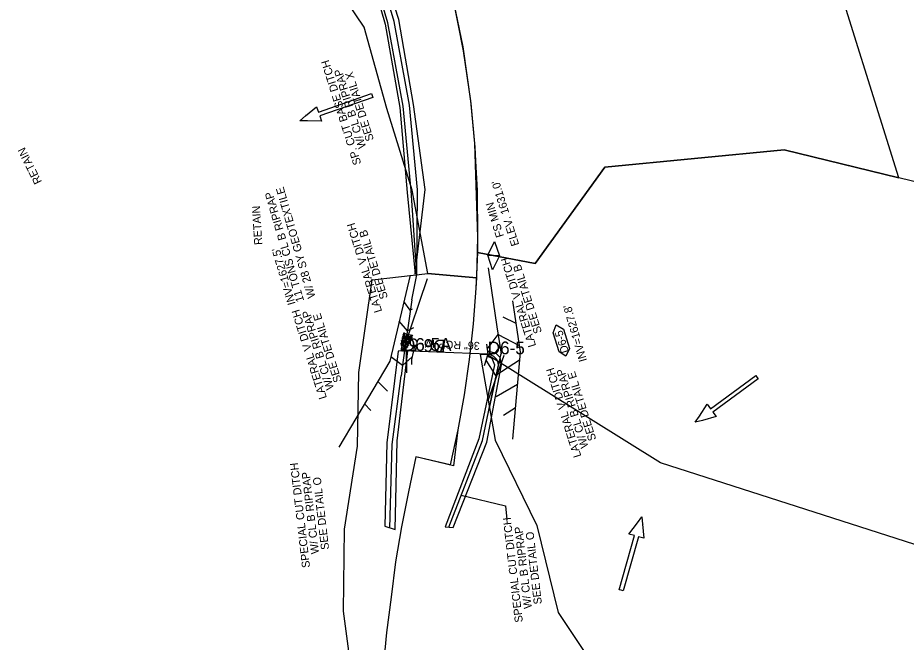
# Model space of a CAD drawing. Extents: x 465700 to 483515, y 488970 to 507540.
# Drawn here: x 474377 to 474932, y 504423 to 504814 of the extents above; entities that cross this region are included whole.
import ezdxf

# ---------------------------------------------------------------- set-up
doc = ezdxf.new("R2010")
doc.units = 0
for name, color, linetype in [('Default', 7, 'Continuous'), ('Exist Plan Preparation Drainage Flow Arrows', 7, 'Continuous'), ('Exist Plan Preparation Watershed Blue', 7, 'Continuous'), ('Prop Drainage Structure Box Number Symbol CELL', 7, 'Continuous'), ('Prop Drainage Structure Pipe Collar Label', 7, 'Continuous'), ('Prop Drainage Structure Pipe RCP 36in Class IV', 7, 'Continuous'), ('Prop Drainage Structure Pipe RCP 36in Class IV Label', 7, 'Continuous'), ('Prop Drainage Structure Pipe Stub Out CELL', 7, 'Continuous'), ('Prop Drainage Structure Tops and Inverts LABEL', 7, 'Continuous'), ('Prop Earthen Structure Ditch Flow Line', 7, 'Continuous'), ('Prop Earthen Structure False Sump CELL', 7, 'Continuous'), ('Prop Earthen Structure False Sump Label', 7, 'Continuous'), ('Prop Earthen Structure Head Ditch', 7, 'Continuous'), ('Prop Erosion Embankment Toe Protection Label', 7, 'Continuous'), ('Prop Erosion Rip Rap Class B', 7, 'Continuous'), ('Prop Erosion Rip Rap Pad at Outlet CELL', 7, 'Continuous'), ('Prop Erosion Rip Rap Pad at Outlet Label', 7, 'Continuous'), ('Scratch_Level_4', 7, 'Continuous'), ('Scratch_Level_8', 7, 'Continuous')]:
    doc.layers.add(name, color=color, linetype=linetype)

# ---------------------------------------------------------------- blocks, each defined once
blk = doc.blocks.new('Existing ground flow arrow')
at = {"layer": 'Default'}
blk.add_line((2.5, -4.33), (2.5, -4.33), dxfattribs=at)
blk.add_lwpolyline([(-1.29, -47.2), (-1.28, -12.53), (-4.77, -12.53), (-1.65, -4.33), (0, 0), (1.65, -4.33), (4.78, -12.53), (1.28, -12.52), (1.29, -47.19), (0, -47.2)], close=True, dxfattribs=at)

msp = doc.modelspace()

# ---------------------------------------------------------------- linework, layer by layer
at = {"layer": 'Exist Plan Preparation Watershed Blue'}
for points in [[(474648.84, 504827.06), (474655.42, 504793.19), (474660.02, 504761.97), (474662.56, 504735.22), (474664.49, 504676.57), (474664.34, 504667.15), (474700.48, 504660.25), (474743.93, 504720.52), (474855.94, 504731.27), (474927.77, 504713.75), (474882, 504859.82)], [(475570.4, 504291.05), (475350.2, 504505.26), (475188.14, 504513.08), (475042.86, 504685.67), (474855.94, 504731.27), (474743.93, 504720.52), (474700.48, 504660.25), (474664.34, 504667.15), (474663.39, 504644.79), (474661.7, 504622.49), (474659.24, 504600.25), (474656.04, 504578.11), (474652.08, 504556.09), (474649.34, 504533.77), (474625.96, 504539.2), (474621.18, 504517.45), (474616.94, 504495.59), (474613.24, 504473.63), (474610.4, 504451.46), (474607.44, 504429.48), (474605.35, 504407.31)]]:
    msp.add_lwpolyline(points, dxfattribs=at)
at = {"layer": 'Prop Drainage Structure Box Number Symbol CELL'}
msp.add_lwpolyline([(474715.42, 504604.91), (474711.65, 504616.94), (474713.51, 504621.82), (474718.1, 504619.12), (474721.87, 504607.09), (474719.65, 504602.21), (474715.42, 504604.91)], dxfattribs=at)
at = {"layer": 'Prop Drainage Structure Pipe RCP 36in Class IV'}
msp.add_line((474670.78, 504603.4), (474617.78, 504605.54), dxfattribs=at)
at = {"layer": 'Prop Drainage Structure Pipe Stub Out CELL'}
msp.add_line((474670.78, 504603.4), (474670.78, 504603.4), dxfattribs=at)
msp.add_line((474670.78, 504603.4), (474670.78, 504603.4), dxfattribs=at)
msp.add_lwpolyline([(474670.77, 504603.4), (474670.79, 504603.42), (474670.8, 504603.4), (474670.78, 504603.39), (474670.77, 504603.4)], dxfattribs=at)
at = {"layer": 'Prop Earthen Structure Ditch Flow Line'}
for p, q in [((474626.39, 504653.19), (474626.84, 504706.28)), ((474671.03, 504657.44), (474676.54, 504620.59))]:
    msp.add_line(p, q, dxfattribs=at)
for points in [[(474622.86, 504705.91), (474617.92, 504758.57), (474608.42, 504810.58), (474593.3, 504861.45), (474572.32, 504910.74)], [(474626.84, 504706.28), (474621.89, 504759.11), (474612.32, 504811.51), (474597.07, 504862.8), (474576, 504912.31)], [(474623.27, 504637.38), (474626.39, 504653.19), (474622.86, 504705.91)], [(474609.67, 504494.69), (474611.07, 504546.92), (474616.75, 504589.94)], [(474646.4, 504495.4), (474667.45, 504549.43), (474674.28, 504581.38)]]:
    msp.add_lwpolyline(points, dxfattribs=at)
at = {"layer": 'Prop Earthen Structure False Sump CELL'}
msp.add_lwpolyline([(474673.71, 504656.14), (474670.78, 504665.4), (474675.04, 504674.02), (474678.14, 504664.92), (474670.78, 504665.4), (474678.14, 504664.92), (474673.71, 504656.14)], dxfattribs=at)
at = {"layer": 'Prop Earthen Structure Head Ditch'}
for p, q in [((474632.84, 504650.7), (474617.77, 504605.54)), ((474632.84, 504650.7), (474617.77, 504605.54)), ((474623.27, 504637.38), (474618.04, 504599.72)), ((474619.8, 504605.47), (474620.11, 504591.74)), ((474671, 504574.44), (474680.98, 504602.77)), ((474618.04, 504599.72), (474616.75, 504589.94))]:
    msp.add_line(p, q, dxfattribs=at)
for points in [[(474622.22, 504652.8), (474609.63, 504599.13), (474577.65, 504545.43)], [(474623.66, 504631.7), (474622.38, 504630.94), (474618.39, 504636.48)], [(474686.32, 504636.79), (474691.15, 504604.83), (474686.28, 504550.27)], [(474680.25, 504626.78), (474688.42, 504622.94)], [(474624.47, 504619.93), (474620.59, 504618.08), (474615.51, 504624.18)], [(474676.54, 504620.59), (474678.29, 504608.9)], [(474676.54, 504620.59), (474679.09, 504603.53)], [(474670.48, 504606.6), (474677.3, 504615.83), (474690.53, 504608.97)], [(474625.19, 504609.42), (474623.13, 504600.14), (474623.06, 504597.12)], [(474670, 504609.75), (474670.9, 504603.41), (474668.55, 504596.22)], [(474671.8, 504569.8), (474679.11, 504603.98)], [(474623.49, 504601.77), (474617.51, 504596.41), (474610.28, 504601.9)], [(474690.69, 504599.66), (474675.95, 504590.11), (474669.71, 504599.75)], [(474674.28, 504581.38), (474677.55, 504596.71)], [(474608.25, 504580.29), (474602.1, 504586.48)], [(474689.34, 504584.53), (474676.05, 504576.78)], [(474597.76, 504568.33), (474593.72, 504572.41)], [(474688.04, 504569.88), (474680.58, 504565.05)]]:
    msp.add_lwpolyline(points, dxfattribs=at)
for centre, radius, start, end in [((474671.48, 504610.33), 6.96, 264.266, 348.169), ((474670.4, 504596.26), 7.17, 3.5869, 85.9655)]:
    msp.add_arc(centre, radius, start, end, dxfattribs=at)
at = {"layer": 'Prop Erosion Embankment Toe Protection Label'}
msp.add_lwpolyline([(474654.24, 504515.42), (474681.83, 504508.62), (474682.8, 504500.11)], dxfattribs=at)
at = {"layer": 'Prop Erosion Rip Rap Class B'}
for p, q in [((474620.79, 504605.5), (474614.8, 504605.36)), ((474606.51, 504495.85), (474612.98, 504493.92)), ((474644.17, 504495.53), (474649.12, 504495.22))]:
    msp.add_line(p, q, dxfattribs=at)
for points in [[(474572.16, 504909.07), (474592.55, 504859), (474606.77, 504809.82), (474615.79, 504757.68), (474620.45, 504704.65), (474625.47, 504653.43), (474631.73, 504706.41), (474624.46, 504759.64), (474615.2, 504812.86), (474599.15, 504862.42), (474577.66, 504912.17)], [(474614.8, 504605.36), (474607.7, 504548.14), (474606.51, 504495.85)], [(474612.98, 504493.92), (474614.23, 504549.28), (474620.79, 504605.5)], [(474679.38, 504596.81), (474678.64, 504601.45), (474675.97, 504603.94), (474670.87, 504605.44), (474670.74, 504602.31), (474673.4, 504600.92), (474675.12, 504596.81)], [(474675.12, 504596.81), (474665.19, 504550.49), (474644.17, 504495.53)], [(474649.12, 504495.22), (474670.29, 504548.5), (474679.38, 504596.81)]]:
    msp.add_lwpolyline(points, dxfattribs=at)
at = {"layer": 'Prop Erosion Rip Rap Pad at Outlet CELL'}
msp.add_line((474617.78, 504605.54), (474617.78, 504605.54), dxfattribs=at)
msp.add_line((474617.78, 504605.54), (474617.78, 504605.54), dxfattribs=at)
for points in [[(474617.82, 504613.94), (474618, 504613.7), (474617.98, 504613.2), (474617.72, 504613.03), (474617.55, 504613.12), (474617.5, 504613.7), (474617.61, 504613.87), (474617.82, 504613.94)], [(474617.69, 504614.61), (474618, 504614.76), (474618.45, 504614.72), (474618.67, 504614.48), (474618.6, 504614.18), (474617.99, 504614.26), (474617.72, 504614.41), (474617.69, 504614.61)], [(474618.65, 504615.11), (474618.33, 504615.08), (474617.96, 504615.29), (474617.87, 504615.66), (474618.03, 504615.81), (474618.61, 504615.66), (474618.7, 504615.29), (474618.65, 504615.11)], [(474618.82, 504613.33), (474618.5, 504613.29), (474618.13, 504613.5), (474618.03, 504613.88), (474618.19, 504614.03), (474618.77, 504613.88), (474618.87, 504613.51), (474618.82, 504613.33)], [(474618.65, 504616.91), (474618.83, 504616.68), (474618.81, 504616.18), (474618.54, 504616.01), (474618.37, 504616.09), (474618.32, 504616.68), (474618.44, 504616.84), (474618.65, 504616.91)], [(474618.9, 504614.61), (474618.71, 504615.08), (474618.66, 504616.1), (474619.26, 504616.49), (474619.74, 504616.24), (474619.74, 504615), (474619.43, 504614.62), (474618.88, 504614.53)], [(474619.27, 504614.15), (474619.41, 504613.94), (474619.43, 504613.38), (474619.15, 504613.22), (474618.98, 504613.31), (474618.91, 504613.94), (474619.03, 504614.1), (474619.27, 504614.15)], [(474619.7, 504612.82), (474619.63, 504613.25), (474619.59, 504614.32), (474620.18, 504614.66), (474620.69, 504614.53), (474620.65, 504613.3), (474620.35, 504612.75), (474619.82, 504612.82)], [(474620.16, 504615.43), (474620.32, 504615.19), (474620.32, 504614.68), (474620.04, 504614.53), (474619.86, 504614.58), (474619.8, 504615.22), (474619.96, 504615.41), (474620.16, 504615.43)], [(474621.02, 504615.21), (474620.65, 504615.24), (474620.03, 504615.4), (474619.97, 504615.96), (474620.12, 504616.22), (474621, 504615.88), (474621.15, 504615.53), (474621.02, 504615.21)], [(474620.81, 504614.39), (474621.19, 504614.48), (474621.91, 504614.41), (474622.12, 504614.04), (474622.03, 504613.75), (474621.19, 504613.75), (474620.85, 504613.95), (474620.81, 504614.39)], [(474622.81, 504614.33), (474622.29, 504614.38), (474621.34, 504614.6), (474621.18, 504615.37), (474621.52, 504615.79), (474622.66, 504615.41), (474622.94, 504614.84), (474622.81, 504614.33)], [(474623.06, 504613.35), (474622.74, 504613.33), (474622.26, 504613.42), (474622.25, 504613.77), (474622.38, 504614.01), (474622.97, 504613.77), (474623.13, 504613.51), (474623.06, 504613.35)], [(474623.53, 504613.85), (474623.22, 504613.85), (474622.73, 504613.93), (474622.72, 504614.29), (474622.85, 504614.52), (474623.45, 504614.29), (474623.6, 504614.02), (474623.53, 504613.85)], [(474623.65, 504614.86), (474623.33, 504614.85), (474622.85, 504614.94), (474622.83, 504615.29), (474622.97, 504615.53), (474623.56, 504615.3), (474623.72, 504615.03), (474623.65, 504614.86)], [(474617.79, 504609.67), (474617.38, 504609.66), (474616.79, 504609.81), (474616.71, 504610.37), (474616.94, 504610.63), (474617.75, 504610.32), (474617.87, 504609.95), (474617.79, 504609.67)], [(474617.22, 504609.66), (474617.4, 504609.43), (474617.38, 504608.93), (474617.11, 504608.76), (474616.94, 504608.85), (474616.9, 504609.44), (474617.01, 504609.61), (474617.22, 504609.66)], [(474617, 504611.96), (474617.23, 504612.09), (474617.66, 504612.1), (474617.9, 504611.83), (474617.83, 504611.52), (474617.22, 504611.6), (474616.96, 504611.78), (474617, 504611.96)], [(474618.67, 504607.3), (474618.17, 504607.32), (474617.18, 504607.57), (474617.02, 504608.32), (474617.31, 504608.66), (474618.49, 504608.28), (474618.77, 504607.77), (474618.67, 504607.3)], [(474617.42, 504611.56), (474617.59, 504611.31), (474617.56, 504610.81), (474617.31, 504610.65), (474617.14, 504610.74), (474617.08, 504611.33), (474617.21, 504611.49), (474617.42, 504611.56)], [(474617.81, 504609.64), (474617.97, 504609.36), (474617.91, 504608.88), (474617.68, 504608.7), (474617.46, 504608.76), (474617.44, 504609.43), (474617.6, 504609.58), (474617.81, 504609.64)], [(474617.68, 504612.87), (474618.2, 504613.01), (474619.37, 504613.17), (474619.81, 504612.32), (474619.69, 504611.85), (474618.2, 504611.8), (474617.59, 504612.26), (474617.55, 504612.9)], [(474618.24, 504611.64), (474618.38, 504611.4), (474618.33, 504610.92), (474618.09, 504610.74), (474617.87, 504610.8), (474617.87, 504611.43), (474618.02, 504611.58), (474618.24, 504611.64)], [(474618.26, 504609.25), (474618.43, 504609.02), (474618.4, 504608.52), (474618.15, 504608.35), (474617.98, 504608.44), (474617.93, 504609.03), (474618.05, 504609.19), (474618.26, 504609.25)], [(474619.27, 504611.1), (474619.82, 504610.45), (474620.45, 504608.82), (474619.67, 504607.9), (474618.84, 504607.88), (474618.01, 504609.87), (474618.37, 504610.78), (474619.19, 504611.25)], [(474619.57, 504611.15), (474619.24, 504611.12), (474618.87, 504611.32), (474618.77, 504611.7), (474618.93, 504611.85), (474619.51, 504611.7), (474619.62, 504611.33), (474619.57, 504611.15)], [(474620.14, 504611.33), (474620.31, 504611.11), (474620.26, 504610.61), (474620.03, 504610.44), (474619.81, 504610.5), (474619.77, 504611.12), (474619.94, 504611.31), (474620.14, 504611.33)], [(474621.49, 504611.14), (474620.95, 504611.18), (474620, 504611.53), (474619.86, 504612.19), (474620.16, 504612.65), (474621.29, 504612.25), (474621.68, 504611.63), (474621.49, 504611.14)], [(474621.29, 504609.86), (474620.95, 504609.72), (474620.25, 504609.7), (474620, 504610.08), (474620.09, 504610.37), (474620.96, 504610.46), (474621.28, 504610.18), (474621.29, 504609.86)], [(474620.44, 504608.55), (474620.57, 504608.28), (474620.56, 504607.78), (474620.32, 504607.62), (474620.1, 504607.68), (474620.08, 504608.33), (474620.23, 504608.5), (474620.44, 504608.55)], [(474621.18, 504609), (474620.86, 504608.99), (474620.38, 504609.08), (474620.37, 504609.43), (474620.5, 504609.67), (474621.09, 504609.43), (474621.25, 504609.17), (474621.18, 504609)], [(474620.42, 504610.99), (474620.65, 504611.04), (474621.18, 504611.11), (474621.28, 504610.75), (474621.24, 504610.59), (474620.6, 504610.52), (474620.44, 504610.67), (474620.42, 504610.99)], [(474621.03, 504613.43), (474621.2, 504613.16), (474621.18, 504612.66), (474620.9, 504612.5), (474620.73, 504612.58), (474620.69, 504613.18), (474620.82, 504613.37), (474621.03, 504613.43)], [(474621.64, 504611.07), (474621.8, 504610.84), (474621.79, 504610.34), (474621.51, 504610.19), (474621.33, 504610.24), (474621.27, 504610.87), (474621.44, 504611.05), (474621.64, 504611.07)], [(474621.79, 504613.55), (474621.81, 504613.35), (474621.89, 504612.82), (474621.53, 504612.68), (474621.35, 504612.73), (474621.3, 504613.4), (474621.55, 504613.5), (474621.79, 504613.55)], [(474621.32, 504612.54), (474621.55, 504612.55), (474622.05, 504612.53), (474622.21, 504612.26), (474622.18, 504612.12), (474621.64, 504612.02), (474621.39, 504612.21), (474621.33, 504612.42)], [(474622.1, 504612.01), (474622.27, 504611.78), (474622.25, 504611.28), (474621.97, 504611.12), (474621.79, 504611.17), (474621.73, 504611.8), (474621.9, 504611.99), (474622.1, 504612.01)], [(474622.47, 504613.33), (474622.59, 504613.02), (474622.6, 504612.51), (474622.34, 504612.4), (474622.17, 504612.44), (474622.09, 504613.09), (474622.26, 504613.27), (474622.47, 504613.33)], [(474616.85, 504605.96), (474617.09, 504605.99), (474617.66, 504606.07), (474617.72, 504605.74), (474617.68, 504605.56), (474617.07, 504605.47), (474616.78, 504605.67), (474616.85, 504605.96)], [(474617.59, 504607.43), (474617.69, 504607.09), (474617.75, 504606.46), (474617.31, 504606.14), (474616.92, 504606.24), (474616.97, 504607.16), (474617.23, 504607.4), (474617.59, 504607.43)], [(474619.63, 504606.12), (474619.2, 504606.05), (474618.17, 504606), (474617.78, 504606.61), (474617.97, 504607.11), (474619.19, 504607.09), (474619.67, 504606.66), (474619.67, 504606.24)], [(474617.86, 504605.83), (474618.09, 504605.84), (474618.62, 504605.94), (474618.73, 504605.61), (474618.68, 504605.43), (474618.03, 504605.32), (474617.78, 504605.54), (474617.86, 504605.83)], [(474619.54, 504607.08), (474619.32, 504607.13), (474618.89, 504607.24), (474618.85, 504607.56), (474618.9, 504607.74), (474619.48, 504607.59), (474619.71, 504607.31), (474619.54, 504607.08)], [(474619.96, 504608.01), (474620.13, 504607.78), (474620.12, 504607.28), (474619.84, 504607.13), (474619.66, 504607.18), (474619.6, 504607.8), (474619.76, 504607.99), (474619.96, 504608.01)]]:
    msp.add_lwpolyline(points, dxfattribs=at)
at = {"layer": 'Scratch_Level_4'}
for points in [[(474927.77, 504713.75), (474882, 504859.82), (474796.36, 504994.66), (474755.09, 505146.54), (474710.28, 505159.29), (474665.31, 505128.41), (474630.64, 505095.35), (474561.34, 505038.16), (474572.33, 505020.45), (474583.42, 505001.22), (474598.56, 504971.69), (474610.53, 504945.48), (474619.28, 504924.18), (474626.52, 504904.71), (474636.37, 504874.75), (474648.84, 504827.06), (474655.42, 504793.19), (474660.02, 504761.97), (474662.65, 504732.92), (474664.1, 504701.99), (474664.34, 504667.15), (474700.48, 504660.25), (474743.93, 504720.52), (474855.94, 504731.27)], [(474663.84, 504651.25), (474633.28, 504653.85), (474623.58, 504706), (474607.64, 504757.06), (474593.52, 504808.01), (474520.92, 504916.02), (474492.44, 504958.4), (474492.4, 504971.95), (474498.69, 504979.98), (474556.41, 505025.69), (474565.17, 505032.64), (474577.08, 505012.49), (474589.92, 504988.88), (474599.32, 504970.23), (474608.48, 504950.2), (474616.75, 504930.77), (474624.17, 504911.28), (474635.54, 504877.68), (474647.27, 504834.08), (474655.13, 504795.67), (474660.26, 504760.3), (474662.56, 504735.22), (474664.17, 504705.93), (474664.49, 504676.57)], [(475270.85, 503809.14), (475219.84, 504084.06), (475137.95, 504274.18), (475078.19, 504412.9), (474954.65, 504479.02), (474778.74, 504535.52), (474670.15, 504603.36), (474666.14, 504603.36), (474675.38, 504549.78), (474701.44, 504496.46), (474714.87, 504441.96), (474760.12, 504373.88), (474867.06, 504270.09), (474948.55, 504177.85), (475007.9, 504065.5), (475074.01, 503992.37), (475126.97, 503907.83)]]:
    msp.add_lwpolyline(points, close=True, dxfattribs=at)
msp.add_lwpolyline([(474587.52, 504391.14), (474580.59, 504442.75), (474581.32, 504494.14), (474589.45, 504545.95), (474590.18, 504592.12), (474598.47, 504649.9), (474633.28, 504653.85), (474663.84, 504651.25), (474663.39, 504644.79), (474661.7, 504622.49), (474659.24, 504600.25), (474656.04, 504578.11), (474652.08, 504556.09), (474647.39, 504534.22), (474625.96, 504539.2), (474621.18, 504517.45), (474616.94, 504495.59), (474613.24, 504473.63), (474610.4, 504451.46), (474607.44, 504429.48), (474605.35, 504407.31)], dxfattribs=at)
at = {"layer": 'Scratch_Level_8'}
msp.add_line((474670.78, 504603.4), (474617.78, 504605.54), dxfattribs=at)

# ---------------------------------------------------------------- block references
at = {"layer": 'Exist Plan Preparation Drainage Flow Arrows'}
for p, xscale, yscale, rotation in [((474553.42, 504749.45), 1.0124070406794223, 1.0124070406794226, 109.32214741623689), ((474800.49, 504560.88), 1.012407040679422, 1.0124070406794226, 126.25082153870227), ((474767.13, 504501.88), 1.012407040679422, 1.0124070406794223, -15.648650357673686)]:
    msp.add_blockref('Existing ground flow arrow', p, dxfattribs=dict(at, xscale=xscale, yscale=yscale, rotation=rotation))

# ---------------------------------------------------------------- texts
at = {"layer": 'Prop Drainage Structure Box Number Symbol CELL'}
msp.add_text('D6-5', height=5, rotation=107.3919, dxfattribs=at).set_placement((474721.56, 504604.99))
at = {"layer": 'Prop Drainage Structure Pipe Collar Label'}
for rotation, p in [(116.5286, (474392.27, 504711.31)), (93.5137, (474529.92, 504671.95))]:
    msp.add_text('RETAIN', height=5, rotation=rotation, dxfattribs=at).set_placement(p)
at = {"layer": 'Prop Drainage Structure Pipe RCP 36in Class IV Label'}
msp.add_text('36" RCP-IV', height=5, rotation=177.6893, dxfattribs=at).set_placement((474665.9, 504611.11))
at = {"layer": 'Prop Drainage Structure Pipe Stub Out CELL'}
msp.add_text('SO', height=0.0104, rotation=355.9935, dxfattribs=at).set_placement((474670.78, 504603.4))
at = {"layer": 'Prop Drainage Structure Tops and Inverts LABEL'}
for s, p in [("INV=1627.5'", (474550.78, 504635.06)), ("INV=1627.8'", (474732.86, 504599.53))]:
    msp.add_text(s, height=5, rotation=106.1785, dxfattribs=at).set_placement(p)
at = {"layer": 'Prop Earthen Structure False Sump Label'}
for s, p in [("ELEV. 1631.0'", (474690.5, 504671.98)), ('FS MIN', (474680.95, 504677.37))]:
    msp.add_text(s, height=5, rotation=107.3948, dxfattribs=at).set_placement(p)
at = {"layer": 'Prop Erosion Embankment Toe Protection Label'}
for s, p in [('SPECIAL CUT DITCH', (474559.78, 504470.19)), ('W/ CL B RIPRAP', (474565.38, 504478.83)), ('SEE DETAIL O', (474571.66, 504481.51)), ('SPECIAL CUT DITCH', (474692.77, 504436.02)), ('W/ CL B RIPRAP', (474698.37, 504444.66)), ('SEE DETAIL O', (474704.65, 504447.34))]:
    msp.add_text(s, height=5, rotation=96.6074, dxfattribs=at).set_placement(p)
at = {"layer": 'Prop Erosion Rip Rap Pad at Outlet Label'}
for s, rotation, p in [('SP. CUT BASE DITCH', 107.389, (474591.79, 504722.65)), ('W/ CL B RIPRAP', 107.389, (474594.84, 504733.01)), ('SEE DETAIL X', 107.389, (474599.7, 504737.57)), ('W/ 28 SY GEOTEXTILE', 106.1785, (474563.22, 504639.29)), ('11 TONS CL B RIPRAP', 106.1785, (474556.09, 504636.95)), ('LATERAL V DITCH', 107.389, (474604.85, 504630.36)), ('SEE DETAIL B', 107.389, (474608.48, 504638.83)), ('LATERAL V DITCH', 107.389, (474701.06, 504608.79)), ('SEE DETAIL B', 107.389, (474704.7, 504617.25)), ('LATERAL V DITCH', 107.389, (474570.32, 504576.23)), ('W/ CL B RIPRAP', 107.389, (474574.78, 504582.08)), ('SEE DETAIL E', 107.389, (474579.63, 504586.67)), ('LATERAL V DITCH', 107.389, (474729.36, 504539.76)), ('W/ CL B RIPRAP', 107.389, (474733.82, 504545.6)), ('SEE DETAIL E', 107.389, (474738.67, 504550.19))]:
    msp.add_text(s, height=5, rotation=rotation, dxfattribs=at).set_placement(p)
at = {"layer": 'Scratch_Level_8'}
for s, p in [('D6-5A', (474617.78, 504605.54)), ('D6-5', (474670.78, 504603.4))]:
    msp.add_text(s, height=8, dxfattribs=at).set_placement(p)
msp.add_text('D6-5', height=8, rotation=177.6893, dxfattribs=at).set_placement((474644.6, 504612.47))

doc.saveas('drawing.dxf')
